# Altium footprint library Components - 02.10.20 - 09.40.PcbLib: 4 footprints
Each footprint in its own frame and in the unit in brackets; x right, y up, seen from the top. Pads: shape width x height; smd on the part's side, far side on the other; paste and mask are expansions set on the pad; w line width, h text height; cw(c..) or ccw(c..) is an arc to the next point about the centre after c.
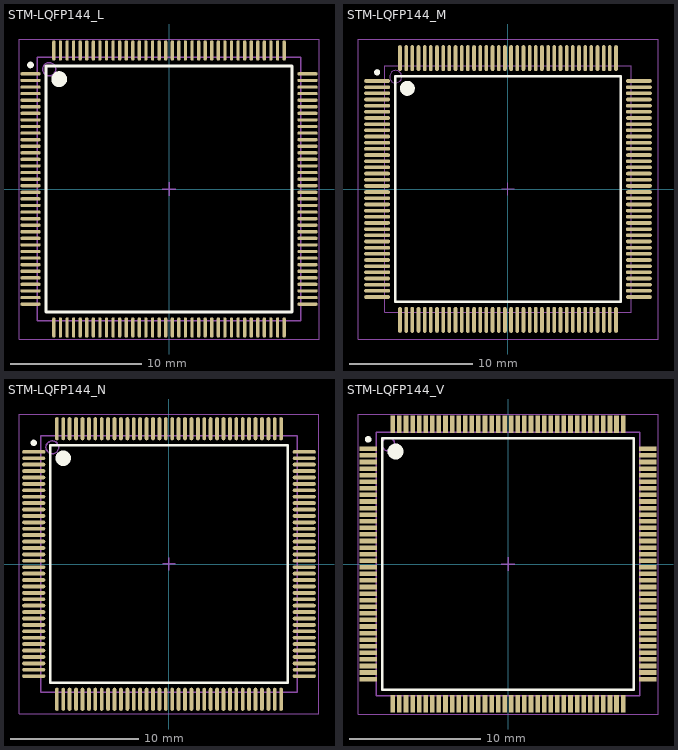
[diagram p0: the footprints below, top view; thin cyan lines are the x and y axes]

## STM-LQFP144_L [mm] "Thin QFP, 144-Leads, Body 20x20mm, Pitch 0.5mm, IPC High Density"
height 1.6
pads (144):
  oval 1.55x0.25 smd: 1(-10.525,8.75) 2(-10.525,8.25) 3(-10.525,7.75) 4(-10.525,7.25) 5(-10.525,6.75) 6(-10.525,6.25) 7(-10.525,5.75) 8(-10.525,5.25) 9(-10.525,4.75) 10(-10.525,4.25) 11(-10.525,3.75) 12(-10.525,3.25) 13(-10.525,2.75) 14(-10.525,2.25) 15(-10.525,1.75) 16(-10.525,1.25) 17(-10.525,0.75) 18(-10.525,0.25) 19(-10.525,-0.25) 20(-10.525,-0.75) 21(-10.525,-1.25) 22(-10.525,-1.75) 23(-10.525,-2.25) 24(-10.525,-2.75) 25(-10.525,-3.25) 26(-10.525,-3.75) 27(-10.525,-4.25) 28(-10.525,-4.75) 29(-10.525,-5.25) 30(-10.525,-5.75) 31(-10.525,-6.25) 32(-10.525,-6.75) 33(-10.525,-7.25) 34(-10.525,-7.75) 35(-10.525,-8.25) 36(-10.525,-8.75) 73(10.525,-8.75) 74(10.525,-8.25) 75(10.525,-7.75) 76(10.525,-7.25) 77(10.525,-6.75) 78(10.525,-6.25) 79(10.525,-5.75) 80(10.525,-5.25) 81(10.525,-4.75) 82(10.525,-4.25) 83(10.525,-3.75) 84(10.525,-3.25) 85(10.525,-2.75) 86(10.525,-2.25) 87(10.525,-1.75) 88(10.525,-1.25) 89(10.525,-0.75) 90(10.525,-0.25) 91(10.525,0.25) 92(10.525,0.75) 93(10.525,1.25) 94(10.525,1.75) 95(10.525,2.25) 96(10.525,2.75) 97(10.525,3.25) 98(10.525,3.75) 99(10.525,4.25) 100(10.525,4.75) 101(10.525,5.25) 102(10.525,5.75) 103(10.525,6.25) 104(10.525,6.75) 105(10.525,7.25) 106(10.525,7.75) 107(10.525,8.25) 108(10.525,8.75)
  oval 0.25x1.55 smd: 37(-8.75,-10.525) 38(-8.25,-10.525) 39(-7.75,-10.525) 40(-7.25,-10.525) 41(-6.75,-10.525) 42(-6.25,-10.525) 43(-5.75,-10.525) 44(-5.25,-10.525) 45(-4.75,-10.525) 46(-4.25,-10.525) 47(-3.75,-10.525) 48(-3.25,-10.525) 49(-2.75,-10.525) 50(-2.25,-10.525) 51(-1.75,-10.525) 52(-1.25,-10.525) 53(-0.75,-10.525) 54(-0.25,-10.525) 55(0.25,-10.525) 56(0.75,-10.525) 57(1.25,-10.525) 58(1.75,-10.525) 59(2.25,-10.525) 60(2.75,-10.525) 61(3.25,-10.525) 62(3.75,-10.525) 63(4.25,-10.525) 64(4.75,-10.525) 65(5.25,-10.525) 66(5.75,-10.525) 67(6.25,-10.525) 68(6.75,-10.525) 69(7.25,-10.525) 70(7.75,-10.525) 71(8.25,-10.525) 72(8.75,-10.525) 109(8.75,10.525) 110(8.25,10.525) 111(7.75,10.525) 112(7.25,10.525) 113(6.75,10.525) 114(6.25,10.525) 115(5.75,10.525) 116(5.25,10.525) 117(4.75,10.525) 118(4.25,10.525) 119(3.75,10.525) 120(3.25,10.525) 121(2.75,10.525) 122(2.25,10.525) 123(1.75,10.525) 124(1.25,10.525) 125(0.75,10.525) 126(0.25,10.525) 127(-0.25,10.525) 128(-0.75,10.525) 129(-1.25,10.525) 130(-1.75,10.525) 131(-2.25,10.525) 132(-2.75,10.525) 133(-3.25,10.525) 134(-3.75,10.525) 135(-4.25,10.525) 136(-4.75,10.525) 137(-5.25,10.525) 138(-5.75,10.525) 139(-6.25,10.525) 140(-6.75,10.525) 141(-7.25,10.525) 142(-7.75,10.525) 143(-8.25,10.525) 144(-8.75,10.525)
Top Overlay:
  circle w0.6: c-8.35,8.35 r0.3
  circle w0.25: c-10.525,9.425 r0.125
  lines w0.2: -9.35,-9.35 9.35,-9.35 9.35,9.35 -9.35,9.35 -9.35,-9.35
Mechanical 13:
  circle w0.1: c-9.1,9.1 r0.5
  lines w0.1: -10,-10 10,-10 10,10 -10,10 -10,-10
Mechanical 15:
  lines w0.05: -11.4,-11.4 11.4,-11.4 11.4,11.4 -11.4,11.4 -11.4,-11.4
  lines w0.1: -0.5,0 0.5,0 ; 0,-0.5 0,0.5
3D body: height 1.6, standoff 0.05, extent -10,-10 10,10

## STM-LQFP144_M [mm] "Thin QFP, 144-Leads, Body 20x20mm, Pitch 0.5mm, IPC Low Density"
height 1.6
pads (144):
  oval 2.1x0.3 smd: 1(-10.6,8.75) 2(-10.6,8.25) 3(-10.6,7.75) 4(-10.6,7.25) 5(-10.6,6.75) 6(-10.6,6.25) 7(-10.6,5.75) 8(-10.6,5.25) 9(-10.6,4.75) 10(-10.6,4.25) 11(-10.6,3.75) 12(-10.6,3.25) 13(-10.6,2.75) 14(-10.6,2.25) 15(-10.6,1.75) 16(-10.6,1.25) 17(-10.6,0.75) 18(-10.6,0.25) 19(-10.6,-0.25) 20(-10.6,-0.75) 21(-10.6,-1.25) 22(-10.6,-1.75) 23(-10.6,-2.25) 24(-10.6,-2.75) 25(-10.6,-3.25) 26(-10.6,-3.75) 27(-10.6,-4.25) 28(-10.6,-4.75) 29(-10.6,-5.25) 30(-10.6,-5.75) 31(-10.6,-6.25) 32(-10.6,-6.75) 33(-10.6,-7.25) 34(-10.6,-7.75) 35(-10.6,-8.25) 36(-10.6,-8.75) 73(10.6,-8.75) 74(10.6,-8.25) 75(10.6,-7.75) 76(10.6,-7.25) 77(10.6,-6.75) 78(10.6,-6.25) 79(10.6,-5.75) 80(10.6,-5.25) 81(10.6,-4.75) 82(10.6,-4.25) 83(10.6,-3.75) 84(10.6,-3.25) 85(10.6,-2.75) 86(10.6,-2.25) 87(10.6,-1.75) 88(10.6,-1.25) 89(10.6,-0.75) 90(10.6,-0.25) 91(10.6,0.25) 92(10.6,0.75) 93(10.6,1.25) 94(10.6,1.75) 95(10.6,2.25) 96(10.6,2.75) 97(10.6,3.25) 98(10.6,3.75) 99(10.6,4.25) 100(10.6,4.75) 101(10.6,5.25) 102(10.6,5.75) 103(10.6,6.25) 104(10.6,6.75) 105(10.6,7.25) 106(10.6,7.75) 107(10.6,8.25) 108(10.6,8.75)
  oval 0.3x2.1 smd: 37(-8.75,-10.6) 38(-8.25,-10.6) 39(-7.75,-10.6) 40(-7.25,-10.6) 41(-6.75,-10.6) 42(-6.25,-10.6) 43(-5.75,-10.6) 44(-5.25,-10.6) 45(-4.75,-10.6) 46(-4.25,-10.6) 47(-3.75,-10.6) 48(-3.25,-10.6) 49(-2.75,-10.6) 50(-2.25,-10.6) 51(-1.75,-10.6) 52(-1.25,-10.6) 53(-0.75,-10.6) 54(-0.25,-10.6) 55(0.25,-10.6) 56(0.75,-10.6) 57(1.25,-10.6) 58(1.75,-10.6) 59(2.25,-10.6) 60(2.75,-10.6) 61(3.25,-10.6) 62(3.75,-10.6) 63(4.25,-10.6) 64(4.75,-10.6) 65(5.25,-10.6) 66(5.75,-10.6) 67(6.25,-10.6) 68(6.75,-10.6) 69(7.25,-10.6) 70(7.75,-10.6) 71(8.25,-10.6) 72(8.75,-10.6) 109(8.75,10.6) 110(8.25,10.6) 111(7.75,10.6) 112(7.25,10.6) 113(6.75,10.6) 114(6.25,10.6) 115(5.75,10.6) 116(5.25,10.6) 117(4.75,10.6) 118(4.25,10.6) 119(3.75,10.6) 120(3.25,10.6) 121(2.75,10.6) 122(2.25,10.6) 123(1.75,10.6) 124(1.25,10.6) 125(0.75,10.6) 126(0.25,10.6) 127(-0.25,10.6) 128(-0.75,10.6) 129(-1.25,10.6) 130(-1.75,10.6) 131(-2.25,10.6) 132(-2.75,10.6) 133(-3.25,10.6) 134(-3.75,10.6) 135(-4.25,10.6) 136(-4.75,10.6) 137(-5.25,10.6) 138(-5.75,10.6) 139(-6.25,10.6) 140(-6.75,10.6) 141(-7.25,10.6) 142(-7.75,10.6) 143(-8.25,10.6) 144(-8.75,10.6)
Top Overlay:
  circle w0.6: c-8.15,8.15 r0.3
  circle w0.25: c-10.6,9.45 r0.125
  lines w0.2: -9.15,-9.15 9.15,-9.15 9.15,9.15 -9.15,9.15 -9.15,-9.15
Mechanical 13:
  circle w0.1: c-9.1,9.1 r0.5
  lines w0.1: -10,-10 10,-10 10,10 -10,10 -10,-10
Mechanical 15:
  lines w0.05: -12.15,-12.15 12.15,-12.15 12.15,12.15 -12.15,12.15 -12.15,-12.15
  lines w0.1: -0.5,0 0.5,0 ; 0,-0.5 0,0.5
3D body: height 1.6, standoff 0.05, extent -10,-10 10,10

## STM-LQFP144_N [mm] "Thin QFP, 144-Leads, Body 20x20mm, Pitch 0.5mm, IPC Medium Density"
height 1.6
pads (144):
  oval 1.8x0.3 smd: 1(-10.55,8.75) 2(-10.55,8.25) 3(-10.55,7.75) 4(-10.55,7.25) 5(-10.55,6.75) 6(-10.55,6.25) 7(-10.55,5.75) 8(-10.55,5.25) 9(-10.55,4.75) 10(-10.55,4.25) 11(-10.55,3.75) 12(-10.55,3.25) 13(-10.55,2.75) 14(-10.55,2.25) 15(-10.55,1.75) 16(-10.55,1.25) 17(-10.55,0.75) 18(-10.55,0.25) 19(-10.55,-0.25) 20(-10.55,-0.75) 21(-10.55,-1.25) 22(-10.55,-1.75) 23(-10.55,-2.25) 24(-10.55,-2.75) 25(-10.55,-3.25) 26(-10.55,-3.75) 27(-10.55,-4.25) 28(-10.55,-4.75) 29(-10.55,-5.25) 30(-10.55,-5.75) 31(-10.55,-6.25) 32(-10.55,-6.75) 33(-10.55,-7.25) 34(-10.55,-7.75) 35(-10.55,-8.25) 36(-10.55,-8.75) 73(10.55,-8.75) 74(10.55,-8.25) 75(10.55,-7.75) 76(10.55,-7.25) 77(10.55,-6.75) 78(10.55,-6.25) 79(10.55,-5.75) 80(10.55,-5.25) 81(10.55,-4.75) 82(10.55,-4.25) 83(10.55,-3.75) 84(10.55,-3.25) 85(10.55,-2.75) 86(10.55,-2.25) 87(10.55,-1.75) 88(10.55,-1.25) 89(10.55,-0.75) 90(10.55,-0.25) 91(10.55,0.25) 92(10.55,0.75) 93(10.55,1.25) 94(10.55,1.75) 95(10.55,2.25) 96(10.55,2.75) 97(10.55,3.25) 98(10.55,3.75) 99(10.55,4.25) 100(10.55,4.75) 101(10.55,5.25) 102(10.55,5.75) 103(10.55,6.25) 104(10.55,6.75) 105(10.55,7.25) 106(10.55,7.75) 107(10.55,8.25) 108(10.55,8.75)
  oval 0.3x1.8 smd: 37(-8.75,-10.55) 38(-8.25,-10.55) 39(-7.75,-10.55) 40(-7.25,-10.55) 41(-6.75,-10.55) 42(-6.25,-10.55) 43(-5.75,-10.55) 44(-5.25,-10.55) 45(-4.75,-10.55) 46(-4.25,-10.55) 47(-3.75,-10.55) 48(-3.25,-10.55) 49(-2.75,-10.55) 50(-2.25,-10.55) 51(-1.75,-10.55) 52(-1.25,-10.55) 53(-0.75,-10.55) 54(-0.25,-10.55) 55(0.25,-10.55) 56(0.75,-10.55) 57(1.25,-10.55) 58(1.75,-10.55) 59(2.25,-10.55) 60(2.75,-10.55) 61(3.25,-10.55) 62(3.75,-10.55) 63(4.25,-10.55) 64(4.75,-10.55) 65(5.25,-10.55) 66(5.75,-10.55) 67(6.25,-10.55) 68(6.75,-10.55) 69(7.25,-10.55) 70(7.75,-10.55) 71(8.25,-10.55) 72(8.75,-10.55) 109(8.75,10.55) 110(8.25,10.55) 111(7.75,10.55) 112(7.25,10.55) 113(6.75,10.55) 114(6.25,10.55) 115(5.75,10.55) 116(5.25,10.55) 117(4.75,10.55) 118(4.25,10.55) 119(3.75,10.55) 120(3.25,10.55) 121(2.75,10.55) 122(2.25,10.55) 123(1.75,10.55) 124(1.25,10.55) 125(0.75,10.55) 126(0.25,10.55) 127(-0.25,10.55) 128(-0.75,10.55) 129(-1.25,10.55) 130(-1.75,10.55) 131(-2.25,10.55) 132(-2.75,10.55) 133(-3.25,10.55) 134(-3.75,10.55) 135(-4.25,10.55) 136(-4.75,10.55) 137(-5.25,10.55) 138(-5.75,10.55) 139(-6.25,10.55) 140(-6.75,10.55) 141(-7.25,10.55) 142(-7.75,10.55) 143(-8.25,10.55) 144(-8.75,10.55)
Top Overlay:
  circle w0.6: c-8.25,8.25 r0.3
  circle w0.25: c-10.55,9.45 r0.125
  lines w0.2: -9.25,-9.25 9.25,-9.25 9.25,9.25 -9.25,9.25 -9.25,-9.25
Mechanical 13:
  circle w0.1: c-9.1,9.1 r0.5
  lines w0.1: -10,-10 10,-10 10,10 -10,10 -10,-10
Mechanical 15:
  lines w0.05: -11.7,-11.7 11.7,-11.7 11.7,11.7 -11.7,11.7 -11.7,-11.7
  lines w0.1: -0.5,0 0.5,0 ; 0,-0.5 0,0.5
3D body: height 1.6, standoff 0.05, extent -10,-10 10,10

## STM-LQFP144_V [mm] "Thin QFP, 144-Leads, Body 20x20mm, Pitch 0.5mm, ST Recommended"
height 1.6
pads (144):
  rect 1.35x0.35 smd: 1(-10.625,8.75) 2(-10.625,8.25) 3(-10.625,7.75) 4(-10.625,7.25) 5(-10.625,6.75) 6(-10.625,6.25) 7(-10.625,5.75) 8(-10.625,5.25) 9(-10.625,4.75) 10(-10.625,4.25) 11(-10.625,3.75) 12(-10.625,3.25) 13(-10.625,2.75) 14(-10.625,2.25) 15(-10.625,1.75) 16(-10.625,1.25) 17(-10.625,0.75) 18(-10.625,0.25) 19(-10.625,-0.25) 20(-10.625,-0.75) 21(-10.625,-1.25) 22(-10.625,-1.75) 23(-10.625,-2.25) 24(-10.625,-2.75) 25(-10.625,-3.25) 26(-10.625,-3.75) 27(-10.625,-4.25) 28(-10.625,-4.75) 29(-10.625,-5.25) 30(-10.625,-5.75) 31(-10.625,-6.25) 32(-10.625,-6.75) 33(-10.625,-7.25) 34(-10.625,-7.75) 35(-10.625,-8.25) 36(-10.625,-8.75) 73(10.625,-8.75) 74(10.625,-8.25) 75(10.625,-7.75) 76(10.625,-7.25) 77(10.625,-6.75) 78(10.625,-6.25) 79(10.625,-5.75) 80(10.625,-5.25) 81(10.625,-4.75) 82(10.625,-4.25) 83(10.625,-3.75) 84(10.625,-3.25) 85(10.625,-2.75) 86(10.625,-2.25) 87(10.625,-1.75) 88(10.625,-1.25) 89(10.625,-0.75) 90(10.625,-0.25) 91(10.625,0.25) 92(10.625,0.75) 93(10.625,1.25) 94(10.625,1.75) 95(10.625,2.25) 96(10.625,2.75) 97(10.625,3.25) 98(10.625,3.75) 99(10.625,4.25) 100(10.625,4.75) 101(10.625,5.25) 102(10.625,5.75) 103(10.625,6.25) 104(10.625,6.75) 105(10.625,7.25) 106(10.625,7.75) 107(10.625,8.25) 108(10.625,8.75)
  rect 0.35x1.35 smd: 37(-8.75,-10.625) 38(-8.25,-10.625) 39(-7.75,-10.625) 40(-7.25,-10.625) 41(-6.75,-10.625) 42(-6.25,-10.625) 43(-5.75,-10.625) 44(-5.25,-10.625) 45(-4.75,-10.625) 46(-4.25,-10.625) 47(-3.75,-10.625) 48(-3.25,-10.625) 49(-2.75,-10.625) 50(-2.25,-10.625) 51(-1.75,-10.625) 52(-1.25,-10.625) 53(-0.75,-10.625) 54(-0.25,-10.625) 55(0.25,-10.625) 56(0.75,-10.625) 57(1.25,-10.625) 58(1.75,-10.625) 59(2.25,-10.625) 60(2.75,-10.625) 61(3.25,-10.625) 62(3.75,-10.625) 63(4.25,-10.625) 64(4.75,-10.625) 65(5.25,-10.625) 66(5.75,-10.625) 67(6.25,-10.625) 68(6.75,-10.625) 69(7.25,-10.625) 70(7.75,-10.625) 71(8.25,-10.625) 72(8.75,-10.625) 109(8.75,10.625) 110(8.25,10.625) 111(7.75,10.625) 112(7.25,10.625) 113(6.75,10.625) 114(6.25,10.625) 115(5.75,10.625) 116(5.25,10.625) 117(4.75,10.625) 118(4.25,10.625) 119(3.75,10.625) 120(3.25,10.625) 121(2.75,10.625) 122(2.25,10.625) 123(1.75,10.625) 124(1.25,10.625) 125(0.75,10.625) 126(0.25,10.625) 127(-0.25,10.625) 128(-0.75,10.625) 129(-1.25,10.625) 130(-1.75,10.625) 131(-2.25,10.625) 132(-2.75,10.625) 133(-3.25,10.625) 134(-3.75,10.625) 135(-4.25,10.625) 136(-4.75,10.625) 137(-5.25,10.625) 138(-5.75,10.625) 139(-6.25,10.625) 140(-6.75,10.625) 141(-7.25,10.625) 142(-7.75,10.625) 143(-8.25,10.625) 144(-8.75,10.625)
Top Overlay:
  circle w0.6: c-8.55,8.55 r0.3
  circle w0.25: c-10.625,9.475 r0.125
  lines w0.2: -9.55,-9.55 9.55,-9.55 9.55,9.55 -9.55,9.55 -9.55,-9.55
Mechanical 13:
  circle w0.1: c-9.1,9.1 r0.5
  lines w0.1: -10,-10 10,-10 10,10 -10,10 -10,-10
Mechanical 15:
  lines w0.05: -11.4,-11.4 11.4,-11.4 11.4,11.4 -11.4,11.4 -11.4,-11.4
  lines w0.1: -0.5,0 0.5,0 ; 0,-0.5 0,0.5
3D body: height 1.6, standoff 0.05, extent -10,-10 10,10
